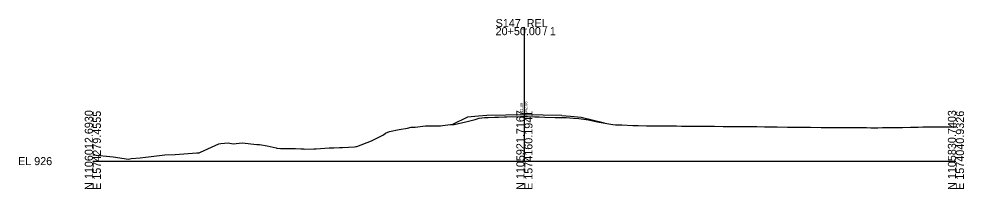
# Model space of a CAD drawing. Extents: x 1557985 to 1558314, y 1113650 to 1118205.
# Drawn here: x 1557985.4 to 1558314, y 1117650.1 to 1117709.1 of the extents above; entities that cross this region are included whole.
import ezdxf

# ---------------------------------------------------------------- set-up
doc = ezdxf.new("R2010")
doc.units = 0
for name, color, linetype in [('RD_GPK_XS_Cell', 7, 'Continuous'), ('RD_XS_EarthShd', 7, 'Continuous'), ('RD_XS_ExGround', 7, 'Continuous'), ('RD_XS_Pave', 7, 'Continuous'), ('RD_XS_TieSlope', 7, 'Continuous'), ('RD_XS_TX_Elev_EX', 7, 'Continuous'), ('RD_XS_TX_Elev_PR', 7, 'Continuous')]:
    doc.layers.add(name, color=color, linetype=linetype)

msp = doc.modelspace()

# ---------------------------------------------------------------- linework, layer by layer
at = {"layer": 'RD_GPK_XS_Cell'}
for p, q in [((1558161.13, 1117659.8), (1558161.13, 1117706.3)), ((1558011.13, 1117659.8), (1558161.13, 1117659.8)), ((1558161.13, 1117659.8), (1558311.13, 1117659.8))]:
    msp.add_line(p, q, dxfattribs=at)
at = {"layer": 'RD_XS_EarthShd'}
for p, q in [((1558145.13, 1117675.38), (1558141.38, 1117675.08)), ((1558148.13, 1117675.62), (1558145.13, 1117675.38)), ((1558174.13, 1117675.62), (1558177.13, 1117675.38)), ((1558177.13, 1117675.38), (1558180.88, 1117675.08))]:
    msp.add_line(p, q, dxfattribs=at)
at = {"layer": 'RD_XS_ExGround'}
msp.add_lwpolyline([(1558011.13, 1117661.94), (1558018.18, 1117661.29), (1558023.54, 1117660.49), (1558024.44, 1117660.69), (1558027.55, 1117660.89), (1558036.2, 1117661.93), (1558039.75, 1117662.1), (1558047.3, 1117662.66), (1558048.07, 1117662.69), (1558048.53, 1117662.85), (1558054.94, 1117665.75), (1558055.67, 1117665.91), (1558058.13, 1117666.18), (1558059.89, 1117665.8), (1558063.05, 1117666.13), (1558068.11, 1117665.59), (1558069.07, 1117665.54), (1558071.73, 1117665.09), (1558074.8, 1117664.37), (1558075.13, 1117664.26), (1558076.4, 1117664.2), (1558079.02, 1117664.17), (1558080.33, 1117664.13), (1558081.6, 1117664.18), (1558083.38, 1117664.07), (1558084.33, 1117664.01), (1558084.7, 1117663.98), (1558087.98, 1117664.02), (1558088.72, 1117664.04), (1558093.32, 1117664.36), (1558094.13, 1117664.41), (1558094.94, 1117664.41), (1558096.81, 1117664.58), (1558097.93, 1117664.56), (1558102.07, 1117664.79), (1558102.52, 1117664.82), (1558102.94, 1117664.9), (1558108.03, 1117666.84), (1558109.79, 1117667.73), (1558112.17, 1117668.97), (1558112.86, 1117669.45), (1558114.2, 1117670.02), (1558117.6, 1117670.81), (1558120.51, 1117671.18), (1558121.75, 1117671.63), (1558123.21, 1117671.62), (1558126.78, 1117672.03), (1558128.78, 1117672.01), (1558131.11, 1117672.02), (1558131.61, 1117672.03), (1558132, 1117672.06), (1558132.66, 1117672.11), (1558135.4, 1117672.45), (1558136.31, 1117672.45), (1558136.74, 1117672.5), (1558141.24, 1117673.59), (1558143.97, 1117674.27), (1558145.41, 1117674.65), (1558147.26, 1117674.9), (1558148.57, 1117674.98), (1558150.91, 1117675.04), (1558152.1, 1117675.07), (1558154.17, 1117675.15), (1558155.01, 1117675.18), (1558159.76, 1117675.28), (1558161.13, 1117675.29), (1558161.75, 1117675.3), (1558162.24, 1117675.27), (1558164.8, 1117675.18), (1558165.45, 1117675.16), (1558166.25, 1117675.11), (1558168.25, 1117675.06), (1558171.87, 1117674.97), (1558175.11, 1117674.94), (1558175.66, 1117674.92), (1558178.17, 1117674.75), (1558180.07, 1117674.62), (1558183.37, 1117674.11), (1558185.95, 1117673.51), (1558187.12, 1117673.37), (1558191.88, 1117672.55), (1558192.75, 1117672.39), (1558194.09, 1117672.38), (1558194.95, 1117672.35), (1558198.88, 1117672.17), (1558200.07, 1117672.12), (1558200.65, 1117672.11), (1558203.58, 1117672.07), (1558205.02, 1117672.05), (1558205.79, 1117672.05), (1558208.14, 1117672.05), (1558208.78, 1117672.05), (1558209.16, 1117672.05), (1558210.09, 1117672.03), (1558212.32, 1117672), (1558213.97, 1117671.99), (1558215.77, 1117671.96), (1558217.31, 1117671.94), (1558219.77, 1117671.89), (1558221.79, 1117671.89), (1558223.42, 1117671.9), (1558225.66, 1117671.92), (1558226.33, 1117671.91), (1558227.19, 1117671.91), (1558230.23, 1117671.87), (1558232.08, 1117671.86), (1558232.72, 1117671.85), (1558235.47, 1117671.82), (1558238.11, 1117671.82), (1558238.83, 1117671.81), (1558240.66, 1117671.8), (1558241.89, 1117671.79), (1558244.55, 1117671.74), (1558244.96, 1117671.74), (1558245.27, 1117671.73), (1558245.82, 1117671.73), (1558248.98, 1117671.73), (1558252.55, 1117671.63), (1558252.91, 1117671.62), (1558254.54, 1117671.62), (1558256.24, 1117671.6), (1558256.75, 1117671.58), (1558259.79, 1117671.56), (1558260.63, 1117671.56), (1558264.29, 1117671.51), (1558266.18, 1117671.5), (1558266.91, 1117671.5), (1558269.57, 1117671.48), (1558270.23, 1117671.5), (1558270.92, 1117671.49), (1558272.1, 1117671.47), (1558273.81, 1117671.45), (1558276.52, 1117671.46), (1558277.25, 1117671.45), (1558278.33, 1117671.45), (1558280.04, 1117671.43), (1558281.6, 1117671.38), (1558283.96, 1117671.38), (1558285.66, 1117671.42), (1558286.88, 1117671.44), (1558288.21, 1117671.45), (1558288.68, 1117671.45), (1558289.26, 1117671.46), (1558291.77, 1117671.5), (1558292.6, 1117671.51), (1558295.38, 1117671.58), (1558297.59, 1117671.62), (1558298, 1117671.62), (1558299.57, 1117671.66), (1558300.77, 1117671.67), (1558304.69, 1117671.69), (1558305.38, 1117671.69), (1558305.68, 1117671.7), (1558307.68, 1117671.71), (1558309.75, 1117671.72), (1558310.16, 1117671.73), (1558310.72, 1117671.73), (1558311.13, 1117671.73)], dxfattribs=at)
at = {"layer": 'RD_XS_Pave'}
for p, q in [((1558161.13, 1117675.88), (1558148.13, 1117675.62)), ((1558174.13, 1117675.62), (1558161.13, 1117675.88))]:
    msp.add_line(p, q, dxfattribs=at)
at = {"layer": 'RD_XS_TieSlope'}
for p, q in [((1558141.38, 1117675.08), (1558136.12, 1117672.45)), ((1558180.88, 1117675.08), (1558189.02, 1117673.04))]:
    msp.add_line(p, q, dxfattribs=at)

# ---------------------------------------------------------------- texts
at = {"layer": 'RD_GPK_XS_Cell'}
for s, p in [('S147_REL', (1558151.13, 1117706.3)), ('20+50.00 / 1', (1558151.13, 1117703.5)), ('EL 926', (1557985.13, 1117658.4))]:
    msp.add_text(s, height=2.8, dxfattribs=at).set_placement(p)
for s, p in [('N 1106012.6930', (1558011.13, 1117649.8)), ('E 1574279.4555', (1558013.93, 1117649.8)), ('N 1105921.7167', (1558161.13, 1117649.8)), ('E 1574160.1941', (1558163.93, 1117649.8)), ('N 1105830.7403', (1558311.13, 1117649.8)), ('E 1574040.9326', (1558313.93, 1117649.8))]:
    msp.add_text(s, height=2.8, rotation=90, dxfattribs=at).set_placement(p)
at = {"layer": 'RD_XS_TX_Elev_EX'}
msp.add_text('941.49', height=1, rotation=90, dxfattribs=at).set_placement((1558160.63, 1117675.79))
at = {"layer": 'RD_XS_TX_Elev_PR'}
msp.add_text(' 942.08', height=1, rotation=90, dxfattribs=at).set_placement((1558162.13, 1117675.88))

doc.saveas('drawing.dxf')
